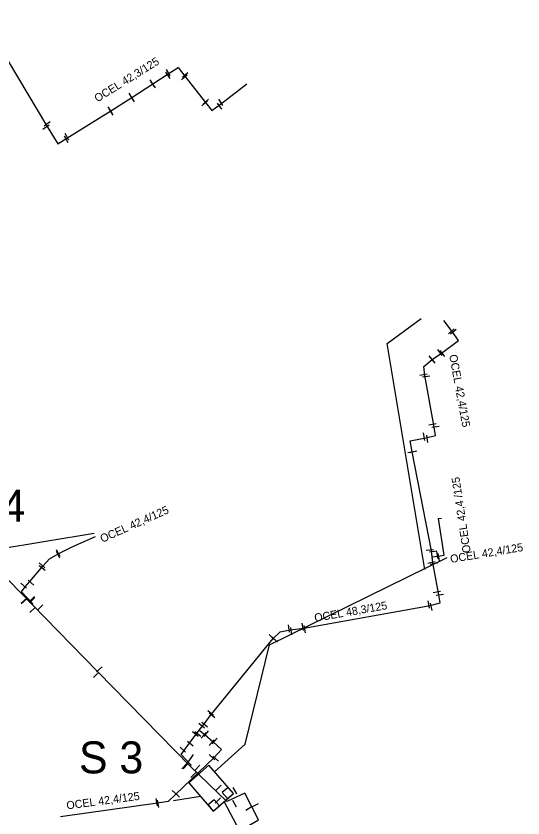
# Model space of a CAD drawing. Extents: x -642943 to -623314, y -1138561 to -1113539.
# Drawn here: x -642268.5 to -642221, y -1114781.1 to -1114705.9 of the extents above; entities that cross this region are included whole.
import ezdxf

# ---------------------------------------------------------------- set-up
doc = ezdxf.new("R2010")
doc.units = 0
for name, color, linetype in [('horkovod dimenze', 7, 'Continuous'), ('horkovod předisol', 7, 'Continuous'), ('horkovod sváry', 7, 'Continuous'), ('horkovod trasa', 7, 'Continuous'), ('horkovod zrušený', 7, 'Continuous'), ('horkovod číslo šachty', 7, 'Continuous'), ('horkovod šachty', 7, 'Continuous')]:
    doc.layers.add(name, color=color, linetype=linetype)

# ---------------------------------------------------------------- blocks, each defined once
blk = doc.blocks.new('SPH_1')
at = {"layer": 'horkovod sváry'}
blk.add_line((0.0001, -0.035), (-0.0001, 0.035), dxfattribs=at)
blk = doc.blocks.new('SPH')
at = {"layer": 'horkovod sváry'}
blk.add_line((0, -0.035), (0, 0.035), dxfattribs=at)
blk = doc.blocks.new('SPH_2')
at = {"layer": 'horkovod sváry'}
blk.add_line((-0.0001, -0.0349), (0.0001, 0.0349), dxfattribs=at)
blk = doc.blocks.new('POINT_DISPLAY')
blk.add_line((0, 0), (0, 0))

msp = doc.modelspace()

# ---------------------------------------------------------------- linework, layer by layer
at = {"layer": 'horkovod předisol'}
msp.add_line((-642267.008, -1114761.085), (-642274.315, -1114753.606), dxfattribs=at)
for points in [[(-642273.2, -1114706.461), (-642272.683, -1114706.265), (-642271.721, -1114705.941), (-642271.051, -1114707.22), (-642265.658, -1114716.189), (-642264.599, -1114717.899), (-642263.777, -1114717.377), (-642259.642, -1114714.823), (-642257.679, -1114713.578), (-642255.715, -1114712.301), (-642254.261, -1114711.369), (-642253.326, -1114710.769), (-642252.703, -1114711.578), (-642250.768, -1114714.043), (-642250.178, -1114714.794), (-642249.367, -1114714.186), (-642246.886, -1114712.297)], [(-642229.527, -1114756.612), (-642229.577, -1114756.034), (-642231.374, -1114746.762), (-642231.578, -1114745.75), (-642230.117, -1114745.45), (-642229.209, -1114745.247), (-642229.35, -1114744.274), (-642230.203, -1114739.62), (-642230.303, -1114738.78), (-642229.511, -1114738.116), (-642228.642, -1114737.512), (-642227.048, -1114736.352), (-642227.634, -1114735.487), (-642228.405, -1114734.482)], [(-642267.008, -1114761.085), (-642266.947, -1114761.028), (-642268.021, -1114759.897), (-642267.669, -1114759.434), (-642267.226, -1114758.935), (-642266.022, -1114757.473), (-642265.38, -1114756.789), (-642264.563, -1114756.341), (-642263.196, -1114755.639), (-642261.085, -1114754.69)], [(-642251.342, -1114772.86), (-642250.985, -1114772.392), (-642250.201, -1114771.363), (-642244.406, -1114764.251), (-642243.776, -1114763.637), (-642242.824, -1114763.449), (-642241.539, -1114763.282), (-642229.708, -1114761.183), (-642228.751, -1114760.928), (-642228.894, -1114760.164), (-642229.463, -1114757.178), (-642229.527, -1114756.612)], [(-642252.188, -1114776.215), (-642260.852, -1114767.391), (-642267.008, -1114761.085)], [(-642251.342, -1114772.86), (-642250.813, -1114773.261), (-642250.04, -1114773.945), (-642249.267, -1114774.675), (-642249.997, -1114775.449), (-642253.541, -1114778.831), (-642254.265, -1114779.522), (-642255.264, -1114779.682), (-642264.363, -1114780.964)], [(-642252.188, -1114776.215), (-642252.1, -1114776.133), (-642253.037, -1114775.13), (-642252.253, -1114774.066), (-642251.342, -1114772.86)], [(-642245.948, -1114785.437), (-642246.214, -1114784.867), (-642247.454, -1114782.219), (-642245.787, -1114781.256), (-642247.074, -1114778.76), (-642248.776, -1114779.538), (-642252.188, -1114776.215)]]:
    msp.add_lwpolyline(points, dxfattribs=at)
at = {"layer": 'horkovod trasa'}
msp.add_line((-642267.008, -1114761.085), (-642274.315, -1114753.606), dxfattribs=at)
for points in [[(-642273.2, -1114706.461), (-642272.683, -1114706.265), (-642271.721, -1114705.941), (-642271.051, -1114707.22), (-642265.658, -1114716.189), (-642264.599, -1114717.899), (-642263.777, -1114717.377), (-642259.642, -1114714.823), (-642257.679, -1114713.578), (-642255.715, -1114712.301), (-642254.261, -1114711.369), (-642253.326, -1114710.769), (-642252.703, -1114711.578), (-642250.768, -1114714.043), (-642250.178, -1114714.794), (-642249.367, -1114714.186), (-642246.886, -1114712.297)], [(-642229.527, -1114756.612), (-642229.577, -1114756.034), (-642231.374, -1114746.762), (-642231.578, -1114745.75), (-642230.117, -1114745.45), (-642229.209, -1114745.247), (-642229.35, -1114744.274), (-642230.203, -1114739.62), (-642230.303, -1114738.78), (-642229.511, -1114738.116), (-642228.642, -1114737.512), (-642227.048, -1114736.352), (-642227.634, -1114735.487), (-642228.405, -1114734.482)], [(-642229.527, -1114756.612), (-642228.936, -1114756.538), (-642228.376, -1114756.446), (-642228.928, -1114753.029), (-642228.644, -1114752.984)], [(-642267.008, -1114761.085), (-642266.947, -1114761.028), (-642268.021, -1114759.897), (-642267.669, -1114759.434), (-642267.226, -1114758.935), (-642266.022, -1114757.473), (-642265.38, -1114756.789), (-642264.563, -1114756.341), (-642263.196, -1114755.639), (-642261.085, -1114754.69)], [(-642251.342, -1114772.86), (-642250.985, -1114772.392), (-642250.201, -1114771.363), (-642244.406, -1114764.251), (-642243.776, -1114763.637), (-642242.824, -1114763.449), (-642241.539, -1114763.282), (-642229.708, -1114761.183), (-642228.751, -1114760.928), (-642228.894, -1114760.164), (-642229.463, -1114757.178), (-642229.527, -1114756.612)], [(-642252.188, -1114776.215), (-642260.852, -1114767.391), (-642267.008, -1114761.085)], [(-642251.342, -1114772.86), (-642250.813, -1114773.261), (-642250.04, -1114773.945), (-642249.267, -1114774.675), (-642249.997, -1114775.449), (-642253.541, -1114778.831), (-642254.265, -1114779.522), (-642255.264, -1114779.682), (-642264.363, -1114780.964)], [(-642252.188, -1114776.215), (-642252.1, -1114776.133), (-642253.037, -1114775.13), (-642252.253, -1114774.066), (-642251.342, -1114772.86)], [(-642245.948, -1114785.437), (-642246.214, -1114784.867), (-642247.454, -1114782.219), (-642245.787, -1114781.256), (-642247.074, -1114778.76), (-642248.776, -1114779.538), (-642252.188, -1114776.215)]]:
    msp.add_lwpolyline(points, dxfattribs=at)
at = {"layer": 'horkovod zrušený'}
for p, q in [((-642271.054, -1114756.01), (-642261.204, -1114754.396)), ((-642251.23, -1114779.052), (-642253.771, -1114779.463)), ((-642246.288, -1114784.693), (-642249.014, -1114779.535))]:
    msp.add_line(p, q, dxfattribs=at)
for points in [[(-642230.215, -1114757.803), (-642233.725, -1114736.635), (-642230.534, -1114734.294)], [(-642249.913, -1114776.745), (-642247.04, -1114774.169), (-642244.777, -1114764.842), (-642228.092, -1114756.681)]]:
    msp.add_lwpolyline(points, dxfattribs=at)
at = {"layer": 'horkovod šachty'}
for p, q in [((-642248.635, -1114778.207), (-642249.2, -1114778.701)), ((-642248.141, -1114778.772), (-642248.635, -1114778.207)), ((-642249.2, -1114778.701), (-642248.706, -1114779.266)), ((-642248.706, -1114779.266), (-642248.141, -1114778.772)), ((-642249.959, -1114779.365), (-642250.524, -1114779.859)), ((-642249.465, -1114779.93), (-642249.959, -1114779.365)), ((-642250.524, -1114779.859), (-642250.03, -1114780.424)), ((-642250.03, -1114780.424), (-642249.465, -1114779.93))]:
    msp.add_line(p, q, dxfattribs=at)
msp.add_lwpolyline([(-642248.141, -1114778.772), (-642250.445, -1114776.137), (-642252.334, -1114777.789), (-642250.03, -1114780.424), (-642248.141, -1114778.772)], dxfattribs=at)

# ---------------------------------------------------------------- block references
at = {"layer": 'horkovod sváry'}
for name, p, xscale, yscale, rotation in [('SPH_1', (-642254.28, -1114711.5), 9.999992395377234, 9.999992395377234, 34.4053543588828), ('SPH_2', (-642254.25, -1114711.25), 9.999982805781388, 9.999982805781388, 31.296409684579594), ('SPH_2', (-642252.67, -1114711.45), 9.999999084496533, 9.999999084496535, -48.29316552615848), ('SPH_1', (-642255.76, -1114712.22), 9.999982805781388, 9.999982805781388, 31.296409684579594), ('SPH_1', (-642255.66, -1114712.39), 9.999992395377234, 9.999992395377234, 34.4053543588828), ('SPH_2', (-642252.75, -1114711.68), 10.000006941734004, 10.000006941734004, -48.53469832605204), ('SPH_1', (-642257.73, -1114713.48), 9.99999947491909, 9.99999947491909, 30.932047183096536), ('SPH_1', (-642257.62, -1114713.67), 9.999986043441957, 9.999986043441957, 32.52947097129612), ('SPH_1', (-642250.83, -1114714.13), 10.000006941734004, 10.000006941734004, -48.53469832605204), ('SPH_1', (-642250.73, -1114713.96), 9.999999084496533, 9.999999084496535, -48.29316552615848), ('SPH_1', (-642249.44, -1114714.38), 9.99999372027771, 9.999993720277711, 36.20948757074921), ('SPH_1', (-642249.32, -1114714.03), 9.999990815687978, 9.99999081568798, 33.855158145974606), ('SPH', (-642259.7, -1114714.74), 9.99999909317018, 9.999999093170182, 30.835363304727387), ('SPH_1', (-642259.6, -1114714.92), 9.999994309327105, 9.999994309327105, 31.053759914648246), ('SPH', (-642265.61, -1114716.02), 9.999978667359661, 9.999978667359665, -55.0531156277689), ('SPH_1', (-642265.72, -1114716.33), 10.00001484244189, 10.000014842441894, -56.14846817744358), ('SPH', (-642263.82, -1114717.51), 9.99999138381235, 9.99999138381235, 29.855643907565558), ('SPH_1', (-642263.75, -1114717.26), 9.99999604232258, 9.999996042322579, 30.285398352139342), ('SPH_1', (-642227.73, -1114735.48), 10.000006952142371, 10.00000695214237, -49.29715829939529), ('SPH_1', (-642227.53, -1114735.5), 10.0000064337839, 10.0000064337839, -51.02347265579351), ('SPH_1', (-642228.77, -1114737.46), 10.00001356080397, 10.000013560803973, 36.60522678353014), ('SPH_1', (-642228.54, -1114737.56), 9.999986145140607, 9.999986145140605, 38.14170185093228), ('SPH_1', (-642229.57, -1114738.04), 9.999975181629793, 9.999975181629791, 39.877855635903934), ('SPH_1', (-642229.46, -1114738.2), 10.000005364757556, 10.000005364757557, 38.39342457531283), ('SPH', (-642230.33, -1114739.52), 9.99998600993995, 9.999986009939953, -80.9340662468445), ('SPH_1', (-642230.08, -1114739.69), 10.000005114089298, 10.000005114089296, -81.2837983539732), ('SPH_1', (-642229.48, -1114744.17), 9.999998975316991, 9.999998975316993, -80.82085479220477), ('SPH_1', (-642229.21, -1114744.42), 9.999995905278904, 9.999995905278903, -83.6466379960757), ('SPH_1', (-642230.26, -1114745.35), 10.000001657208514, 10.000001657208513, 10.296088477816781), ('SPH', (-642229.98, -1114745.55), 9.999997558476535, 9.999997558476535, 7.611093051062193), ('SPH_1', (-642231.46, -1114746.77), 10.000016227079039, 10.000016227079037, -78.70084639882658), ('SPH_1', (-642231.29, -1114746.76), 10.000003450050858, 10.000003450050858, -78.33001895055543), ('SPH_1', (-642264.57, -1114756.43), 10.000027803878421, 10.000027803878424, 27.299595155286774), ('SPH_1', (-642264.56, -1114756.26), 9.999977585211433, 9.99997758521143, 29.045870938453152), ('SPH', (-642229.72, -1114755.98), 9.999982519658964, 9.999982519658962, 96.77287034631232), ('SPH_1', (-642229.43, -1114756.1), 9.999991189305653, 9.99999118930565, -82.65987811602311), ('SPH_1', (-642229, -1114756.45), 10.00000897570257, 10.000008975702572, 9.85870975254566), ('SPH_1', (-642228.89, -1114756.63), 9.999980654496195, 9.999980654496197, 8.822047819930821), ('SPH', (-642266.1, -1114757.41), 10.000005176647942, 10.000005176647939, 48.97257435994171), ('SPH_1', (-642229.57, -1114757.13), 9.999996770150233, 9.999996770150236, -77.53141445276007), ('SPH_1', (-642229.36, -1114757.23), 9.999988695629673, 9.999988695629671, -79.444821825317), ('SPH_1', (-642266.08, -1114757.67), 9.999991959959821, 9.99999195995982, 51.03884788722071), ('SPH_1', (-642267.8, -1114759.32), 10.000005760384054, 10.000005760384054, 48.60728486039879), ('SPH_1', (-642267.12, -1114759.03), 9.999986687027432, 9.999986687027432, 48.01768587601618), ('SPH_1', (-642229.08, -1114759.88), 9.999981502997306, 9.999981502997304, -79.87007533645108), ('SPH', (-642228.79, -1114760.15), 10.000004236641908, 10.000004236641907, -82.38056752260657), ('SPH_1', (-642267.78, -1114760.72), 9.999981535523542, 9.999981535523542, -46.603817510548), ('SPH_1', (-642267.78, -1114760.77), 10.000021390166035, 10.000021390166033, -46.6451440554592), ('SPH_1', (-642267.04, -1114760.58), 10.000017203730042, 10.000017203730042, -44.63814943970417), ('SPH', (-642267.02, -1114760.67), 10.000009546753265, 10.000009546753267, -44.15760612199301), ('SPH_1', (-642229.83, -1114761.08), 9.999992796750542, 9.99999279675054, 9.538248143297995), ('SPH_1', (-642229.59, -1114761.29), 10.000016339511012, 10.00001633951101, 10.239674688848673), ('SPH', (-642266.99, -1114761.59), 10.000001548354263, 10.00000154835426, -44.56928654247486), ('SPH_1', (-642266.27, -1114761.36), 9.999999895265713, 9.999999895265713, -47.19842171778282), ('SPH_1', (-642242.93, -1114763.33), 9.999983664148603, 9.999983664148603, 9.321348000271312), ('SPH_1', (-642242.72, -1114763.57), 10.000001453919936, 10.000001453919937, 6.222101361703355), ('SPH_1', (-642241.63, -1114763.17), 9.999982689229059, 9.999982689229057, 9.618078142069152), ('SPH', (-642241.44, -1114763.38), 10.000012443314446, 10.000012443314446, 9.89770429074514), ('SPH_1', (-642244.54, -1114764.14), 9.999995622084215, 9.999995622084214, 45.308459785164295), ('SPH_1', (-642244.28, -1114764.35), 10.0000112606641, 10.0000112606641, 46.47679917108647), ('SPH', (-642260.71, -1114767.16), 10.00000270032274, 10.00000270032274, -48.37782716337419), ('SPH', (-642261.02, -1114767.65), 10.000009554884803, 10.000009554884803, -44.5887193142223), ('SPH_1', (-642250.27, -1114771.25), 9.999982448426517, 9.999982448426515, 49.4632974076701), ('SPH_1', (-642250.15, -1114771.47), 10.00002239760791, 10.00002239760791, 50.44667282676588), ('SPH_1', (-642251.13, -1114772.44), 10.000015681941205, 10.000015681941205, 49.53784415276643), ('SPH', (-642250.85, -1114772.35), 9.999999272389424, 9.999999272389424, 49.57702798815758), ('SPH', (-642251.72, -1114773.23), 10.000004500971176, 10.000004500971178, 50.08159561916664), ('SPH_1', (-642251.48, -1114773.22), 10.000009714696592, 10.000009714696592, 50.10318534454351), ('SPH_1', (-642250.7, -1114773.19), 10.000017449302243, 10.000017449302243, -40.94289243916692), ('SPH_1', (-642250.93, -1114773.33), 9.999980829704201, 9.999980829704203, -42.35744890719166), ('SPH_1', (-642250.19, -1114774.02), 10.000009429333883, 10.000009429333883, -42.08924520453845), ('SPH_1', (-642249.9, -1114773.87), 9.999995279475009, 9.99999527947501, -41.651840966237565), ('SPH_1', (-642252.89, -1114774.69), 10.00000783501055, 10.00000783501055, 47.87694212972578), ('SPH_1', (-642252.18, -1114774.12), 9.9999891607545, 9.9999891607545, 51.20847926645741), ('SPH_1', (-642252.1, -1114775.43), 9.999987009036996, 9.999987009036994, -34.99210762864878), ('SPH_1', (-642250.15, -1114775.38), 9.999980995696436, 9.999980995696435, 46.73952176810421), ('SPH_1', (-642252.75, -1114776.22), 9.999994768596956, 9.999994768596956, -42.84707690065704), ('SPH_1', (-642252.63, -1114776.23), 9.999992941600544, 9.999992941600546, -43.26444398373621), ('SPH_1', (-642252.28, -1114775.68), 9.999996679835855, 9.999996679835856, -35.69005677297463), ('SPH_1', (-642249.82, -1114775.52), 9.99999035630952, 9.99999035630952, 48.00011520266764), ('SPH_1', (-642251.53, -1114776.37), 9.999999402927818, 9.999999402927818, -43.2819984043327), ('SPH', (-642251.89, -1114777.04), 10.000014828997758, 10.000014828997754, -45.98617004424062), ('SPH_1', (-642249.54, -1114778.24), 10.000020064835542, 10.000020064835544, -45.39297987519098), ('SPH_1', (-642247.99, -1114778.51), 9.999986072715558, 9.999986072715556, 30.28635863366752), ('SPH_1', (-642253.62, -1114778.75), 9.99998543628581, 9.99998543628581, 47.68372215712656), ('SPH_1', (-642253.46, -1114778.9), 9.999987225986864, 9.999987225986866, 46.231476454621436), ('SPH_1', (-642255.32, -1114779.61), 9.999995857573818, 9.999995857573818, 10.346536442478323), ('SPH_1', (-642255.19, -1114779.76), 10.000019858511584, 10.00001985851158, 10.496257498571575), ('SPH_1', (-642249.6, -1114779.44), 10.000004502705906, 10.000004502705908, -45.684472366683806), ('SPH_1', (-642248.03, -1114779.75), 9.999998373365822, 9.99999837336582, 30.13164279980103), ('SPH_1', (-642246.1, -1114779.87), 10.000019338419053, 10.000019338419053, -62.49181307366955), ('SPH', (-642246.68, -1114780.16), 9.999989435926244, 9.999989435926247, -56.49655675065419)]:
    msp.add_blockref(name, p, dxfattribs=dict(at, xscale=xscale, yscale=yscale, rotation=rotation))
at = {"layer": 'horkovod šachty'}
for p in [(-642248.67, -1114778.73), (-642249.994, -1114779.888)]:
    msp.add_blockref('POINT_DISPLAY', p, dxfattribs=at)

# ---------------------------------------------------------------- texts
at = {"layer": 'horkovod dimenze'}
for s, height, rotation, p in [('OCEL 42,3/125', 0.75, 31.89079, (-642260.89, -1114714.044)), ('OCEL 42,4/125', 0.75, 280.42206, (-642227.921, -1114737.716)), ('OCEL 42,4 /125', 0.74998, 98.57497, (-642225.891, -1114756.191)), ('OCEL 42,4/125', 0.75, 24.03989, (-642260.436, -1114755.294)), ('OCEL 42,4/125', 0.75, 9.45135, (-642227.757, -1114757.189)), ('OCEL 48,3/125', 0.75, 10.00246, (-642240.489, -1114762.705)), ('OCEL 42,4/125', 0.74999, 7.52302, (-642263.752, -1114780.277))]:
    msp.add_text(s, height=height, rotation=rotation, dxfattribs=at).set_placement(p)
at = {"layer": 'horkovod číslo šachty'}
for s, p in [('S 4', (-642273.669, -1114753.326)), ('S 3', (-642262.621, -1114776.9))]:
    msp.add_text(s, height=3, dxfattribs=at).set_placement(p)

doc.saveas('drawing.dxf')
